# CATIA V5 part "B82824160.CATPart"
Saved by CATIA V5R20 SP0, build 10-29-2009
Part number: B82824160
Revision: 5
Definition: design
Nomenclature: B82824160
Source: made
Description: NOT SPECIFIED
Bounding box of the stored display mesh (mm): x -14 to 14, y -14 to 14, z 0 to 160
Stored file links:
  C:\Users\Raffaele\Desktop\3D X SITO CF\BOLEX\7-PILLAR REF 828\B82824160.CATPart
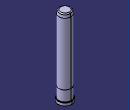
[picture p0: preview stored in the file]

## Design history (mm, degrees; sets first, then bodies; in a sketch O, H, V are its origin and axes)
Body1 "MANIFOLD_SOLID_BREP #450" (main body)
  Solid1: solid without history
